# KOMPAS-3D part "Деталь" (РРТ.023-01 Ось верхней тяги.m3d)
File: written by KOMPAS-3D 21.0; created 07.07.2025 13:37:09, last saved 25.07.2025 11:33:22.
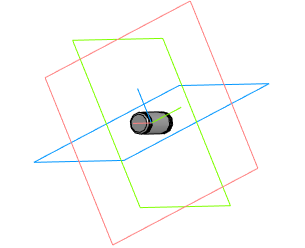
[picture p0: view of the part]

Document properties: Автор: User; Полное имя файла: C:\Users\User\Desktop\Ручной ротатор КД\Модели КД\РРТ.023-01 Ось верхней тяги.m3d

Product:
- Part/product: Деталь
    Масса: 0.002935
    Форматы листов документа: A4

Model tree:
1. Эскиз:1
2. Элемент выдавливания:1
     Расстояние 1 = 14
3. Фаска:1  (with: Элемент выдавливания:1)
     Угол = 45; Длина 1 = 0.5; Длина 2 = 0.5
4. Эскиз:2  (with: Элемент выдавливания:1)
5. Элемент вращения:1  (with: Элемент выдавливания:1)
     Угол 1 = 360
6. Фаска:2  (with: Элемент вращения:1)
     Угол = 45; Длина 1 = 0.2; Длина 2 = 0.2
